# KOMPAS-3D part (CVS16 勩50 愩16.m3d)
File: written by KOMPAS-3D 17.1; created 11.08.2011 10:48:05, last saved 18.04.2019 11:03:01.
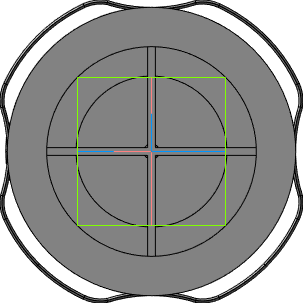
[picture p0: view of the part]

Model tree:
1. Плоскость XY
2. Плоскость ZX
3. Плоскость ZY
4. Ось X
5. Ось Y
6. Ось Z
7. Начало координат
8. Операция без истории:2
